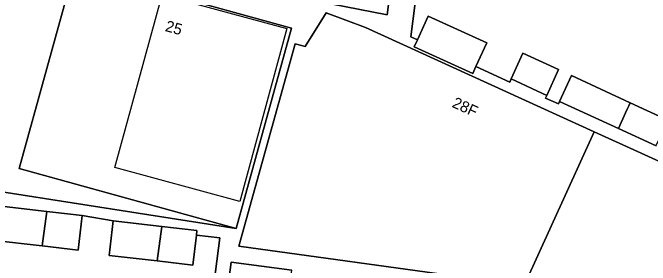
# Model space of a CAD drawing. Extents: x 161838 to 162344, y 381620 to 382160.
# Drawn here: x 161971.9 to 162029.1, y 381724.4 to 381747 of the extents above; entities that cross this region are included whole.
import ezdxf

# ---------------------------------------------------------------- set-up
doc = ezdxf.new("R2010")
doc.units = 0
for name, color, linetype in [('IMGEO_Erf', 7, 'Continuous'), ('IMGEO_Pand', 7, 'Continuous'), ('IMGEO_Pand_nummerreeks', 7, 'Continuous'), ('IMGEO_Pand_vergunning_verleend', 7, 'Continuous'), ('IMGEO_Rijbaan_lokaal_open', 7, 'Continuous'), ('IMGEO_Voetpad_open', 7, 'Continuous')]:
    doc.layers.add(name, color=color, linetype=linetype)

msp = doc.modelspace()

# ---------------------------------------------------------------- linework, layer by layer
at = {"layer": 'IMGEO_Erf'}
for points in [[(161988.151, 381750.259), (162005.486, 381746.869), (162007.054, 381759.154)], [(162009.289, 381758.044), (162007.608, 381744.889), (162008.191, 381744.624), (162009.157, 381746.749), (162014.413, 381744.36), (162013.438, 381742.214), (162016.491, 381740.826), (162016.617, 381741.106), (162017.661, 381743.424), (162020.841, 381741.955), (162019.797, 381739.636), (162019.685, 381739.388), (162020.844, 381738.865), (162020.953, 381739.101), (162022.021, 381741.41), (162027.287, 381738.976), (162030.667, 381737.414)], [(161963.918, 381750), (161962.379, 381738.634), (161961.501, 381732.448), (161991.926, 381727.689), (161972.452, 381733.08), (161977.428, 381751.055)], [(161971.448, 381722.434), (161974.011, 381722.1), (161976.41, 381721.787), (161975.72, 381716.496), (161978.474, 381716.137), (161980.971, 381715.811), (161981.663, 381721.117), (161984.319, 381720.77), (161986.802, 381720.446), (161986.112, 381715.156), (161988.901, 381714.793), (161990.474, 381726.878), (161988.362, 381727.119), (161988.055, 381724.426), (161984.846, 381724.791), (161980.529, 381725.282), (161980.881, 381728.381), (161978.103, 381728.872), (161977.75, 381725.774), (161974.539, 381726.139), (161970.224, 381726.63)]]:
    msp.add_lwpolyline(points, dxfattribs=at)
msp.add_lwpolyline([(161993.945, 381722.758), (161996.728, 381722.396), (161996.932, 381723.958), (161991.473, 381724.669), (161990.054, 381713.77), (161992.728, 381713.422), (161993.711, 381720.964)], close=True, dxfattribs=at)
at = {"layer": 'IMGEO_Pand'}
for points in [[(161991.926, 381727.689), (161996.902, 381745.663), (161977.428, 381751.055), (161972.452, 381733.08)], [(162024.059, 381736.377), (162003.547, 381745.723), (162000, 381747.039), (161998.107, 381744.019), (161997.212, 381744.268), (161992.167, 381726.115), (162012.543, 381723.321), (162017.783, 381722.602)], [(162014.413, 381744.36), (162009.157, 381746.749), (162008.191, 381744.624), (162007.902, 381743.988), (162013.158, 381741.599), (162013.438, 381742.214)], [(162016.617, 381741.106), (162019.797, 381739.636), (162020.841, 381741.955), (162017.661, 381743.424)], [(162027.287, 381738.976), (162022.021, 381741.41), (162020.953, 381739.101), (162026.239, 381736.658), (162026.877, 381738.07), (162027.052, 381738.456), (162027.156, 381738.686)], [(162027.287, 381738.976), (162027.156, 381738.686), (162027.052, 381738.456), (162026.877, 381738.07), (162026.239, 381736.658), (162029.6, 381735.104), (162029.612, 381735.131), (162030.533, 381737.125), (162030.667, 381737.414)], [(161974.539, 381726.139), (161974.942, 381729.232), (161970.576, 381729.729), (161970.224, 381726.63)], [(161974.539, 381726.139), (161977.75, 381725.774), (161978.103, 381728.872), (161974.942, 381729.232)], [(161984.846, 381724.791), (161985.251, 381727.884), (161980.881, 381728.381), (161980.529, 381725.282)], [(161988.362, 381727.119), (161988.408, 381727.524), (161985.251, 381727.884), (161984.846, 381724.791), (161988.055, 381724.426)]]:
    msp.add_lwpolyline(points, close=True, dxfattribs=at)
at = {"layer": 'IMGEO_Pand_vergunning_verleend'}
msp.add_lwpolyline([(161981.052, 381733.177), (161985.285, 381748.692), (161996.486, 381745.635), (161992.252, 381730.121)], close=True, dxfattribs=at)
at = {"layer": 'IMGEO_Rijbaan_lokaal_open'}
msp.add_lwpolyline([(162032.161, 381732.685), (162024.059, 381736.377), (162017.783, 381722.602), (162012.543, 381723.321), (162012.365, 381722.027), (162012.283, 381721.428), (162015.407, 381721.012), (162020.994, 381720.268), (162024.893, 381720.414), (162036.024, 381717.58)], dxfattribs=at)
at = {"layer": 'IMGEO_Voetpad_open'}
for points in [[(162007.054, 381759.154), (162005.486, 381746.869), (161988.151, 381750.259)], [(162029.6, 381735.104), (162026.239, 381736.658), (162020.953, 381739.101), (162020.844, 381738.865), (162019.685, 381739.388), (162019.797, 381739.636), (162016.617, 381741.106), (162016.491, 381740.826), (162013.438, 381742.214), (162013.158, 381741.599), (162007.902, 381743.988), (162008.191, 381744.624), (162007.608, 381744.889), (162009.289, 381758.044)], [(161977.428, 381751.055), (161996.902, 381745.663), (161991.926, 381727.689), (161961.501, 381732.448)], [(162012.543, 381723.321), (161992.167, 381726.115), (161997.212, 381744.268), (161998.107, 381744.019), (162000, 381747.039), (162003.547, 381745.723), (162024.059, 381736.377), (162032.161, 381732.685)], [(161970.576, 381729.729), (161974.942, 381729.232), (161978.103, 381728.872), (161980.881, 381728.381), (161985.251, 381727.884), (161988.408, 381727.524), (161988.362, 381727.119), (161990.474, 381726.878), (161988.901, 381714.793)], [(161990.054, 381713.77), (161991.473, 381724.669), (161996.932, 381723.958)]]:
    msp.add_lwpolyline(points, dxfattribs=at)

# ---------------------------------------------------------------- texts
at = {"layer": 'IMGEO_Pand_nummerreeks'}
for s, rotation, p in [('25', 344.5235, (161985.496, 381745.418)), ('28F', 335.5061, (162011.228, 381738.619))]:
    msp.add_text(s, height=1, rotation=rotation, dxfattribs=at).set_placement(p)

doc.saveas('drawing.dxf')
